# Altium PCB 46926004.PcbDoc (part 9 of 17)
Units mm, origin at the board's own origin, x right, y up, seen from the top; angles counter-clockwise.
Board outline 250 x 200 mm, 6 copper layers (Top Layer, INT1_GND, INT2_SIG, INT3_SIG, INT4_GND, Bottom Layer), stack 1.71 mm thick; 1450 components, 1293 nets, 5656 pads, 2307 vias.
Unrouted connection lines stored in the file: 2.
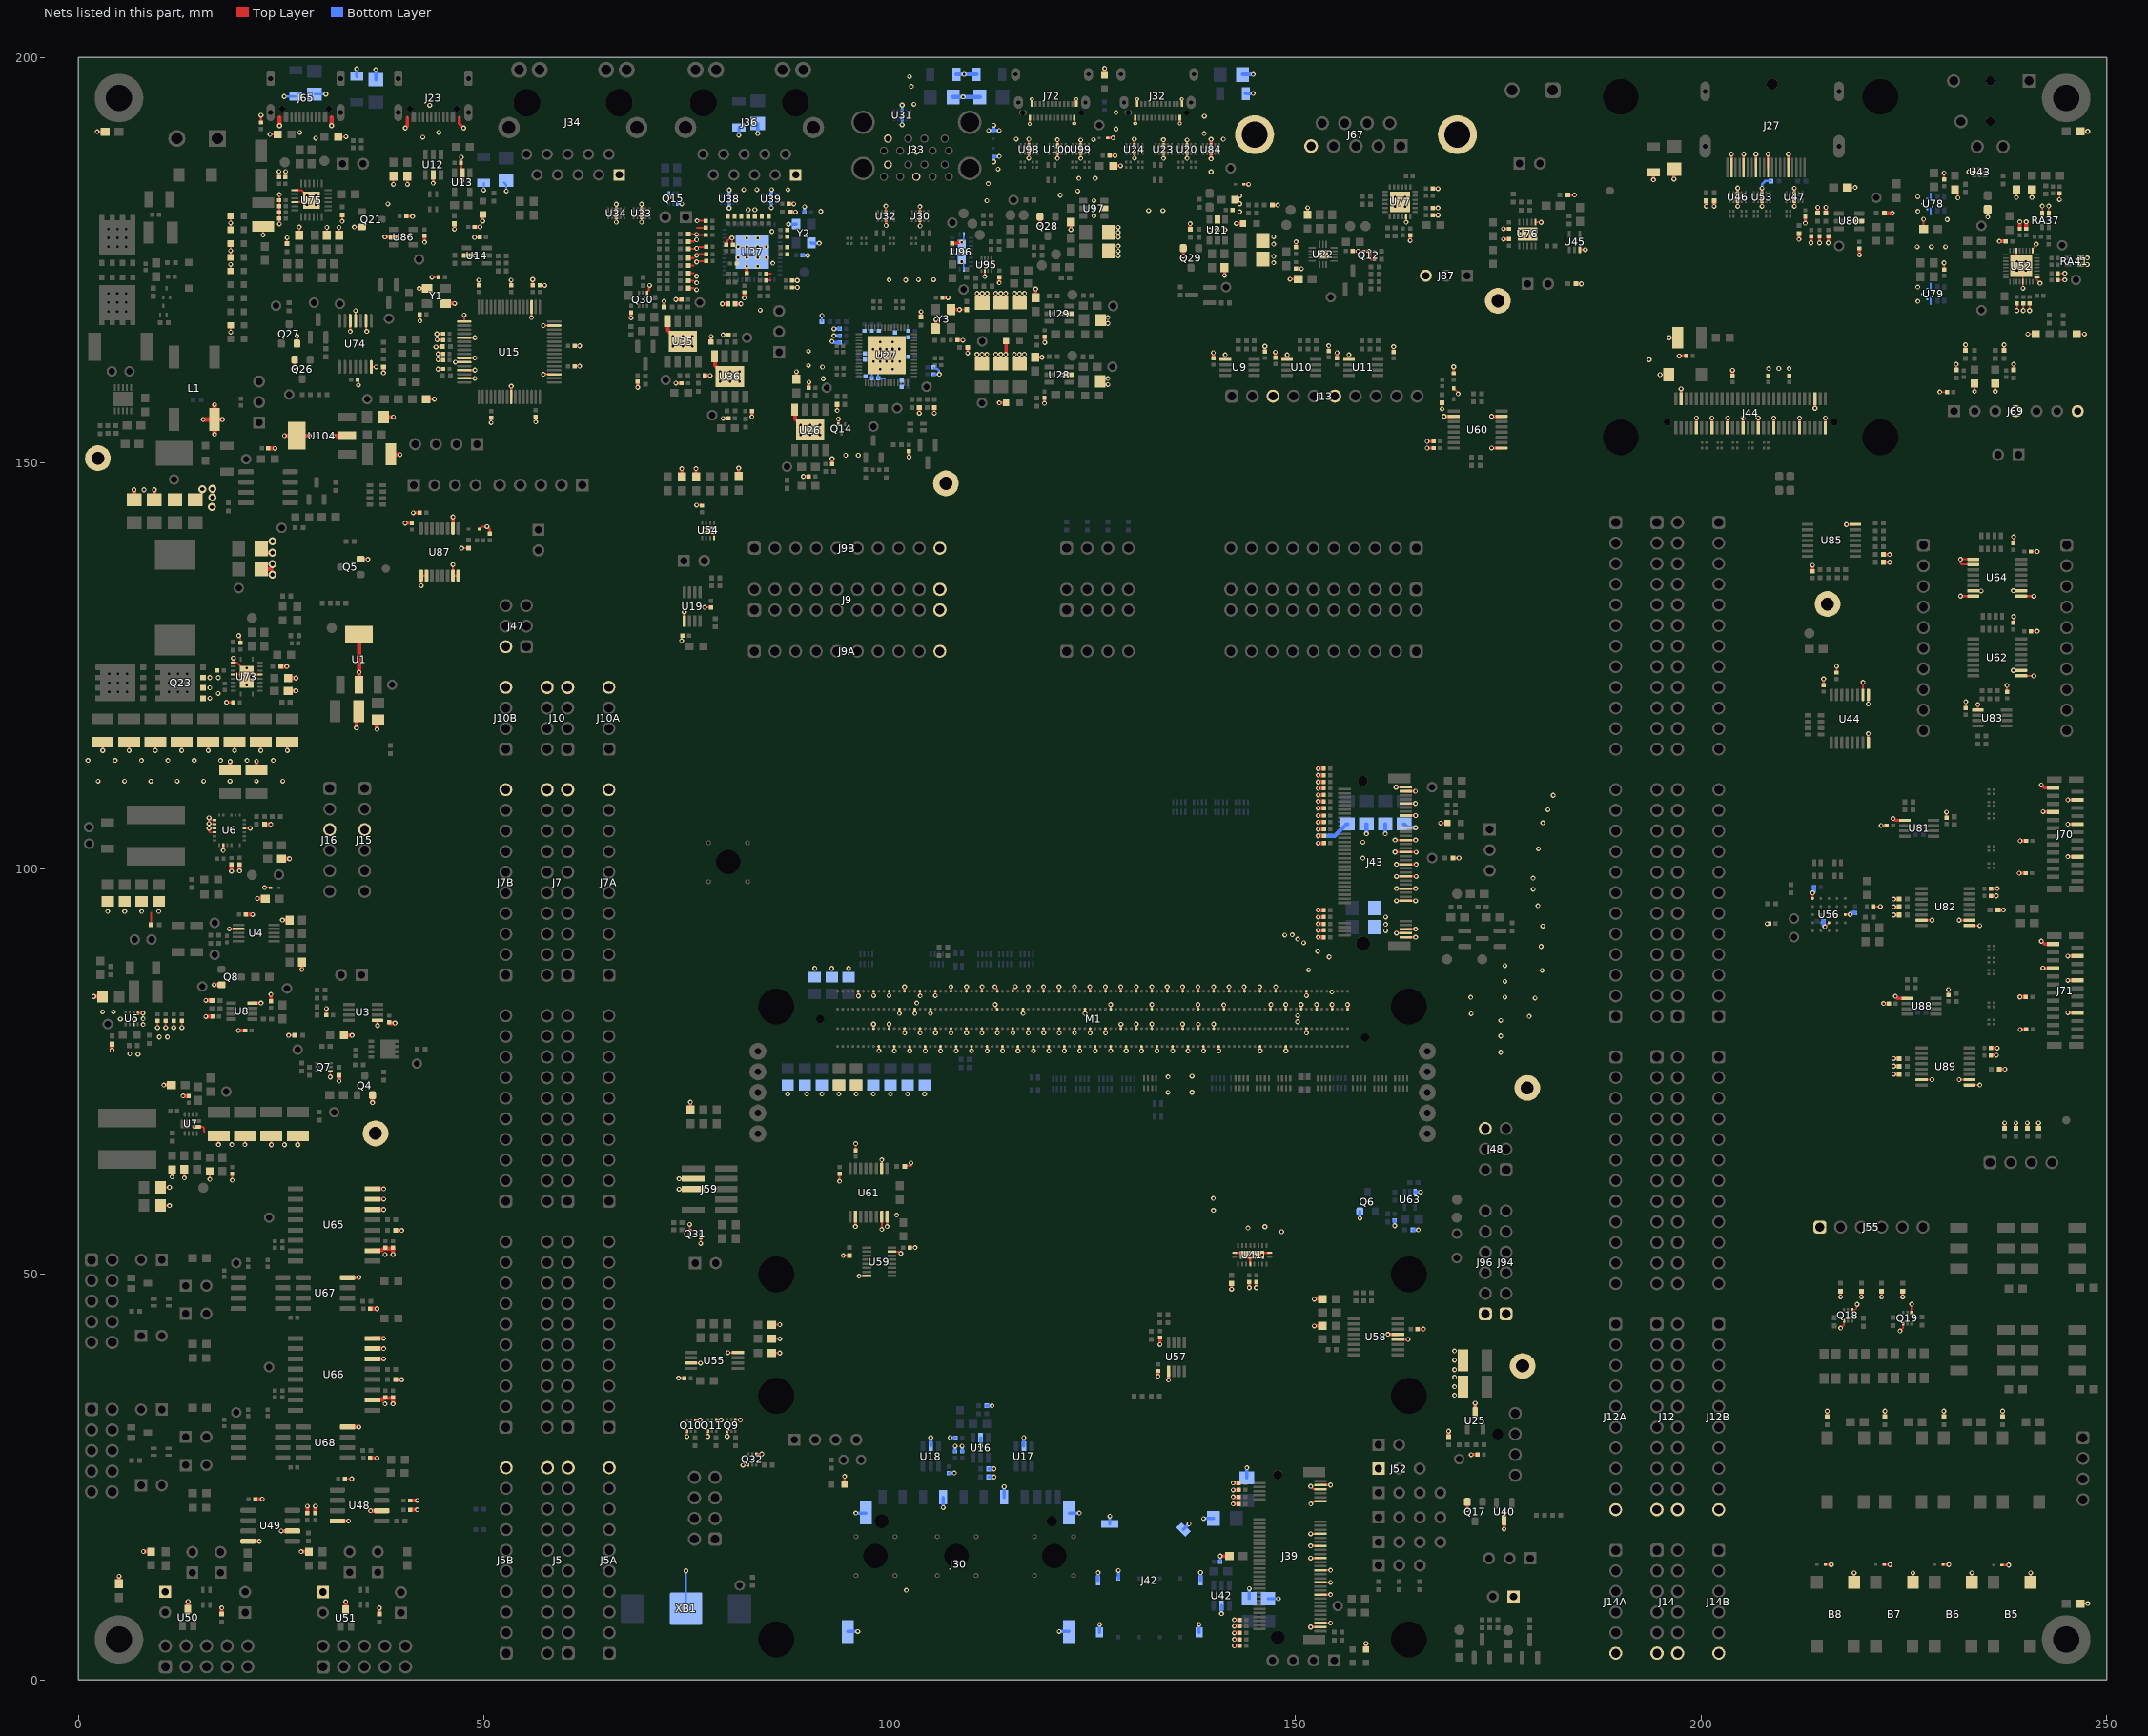
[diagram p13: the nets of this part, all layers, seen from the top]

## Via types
v1: diameter 0.6, hole 0.3, Top Layer to Bottom Layer, tented both sides, 2171 vias
v2: diameter 0.6, hole 0.3, Top Layer to Bottom Layer, 48 vias
v3: diameter 1, hole 0.5, Top Layer to Bottom Layer, tented both sides, 37 vias
v4: diameter 0.5, hole 0.2, Top Layer to Bottom Layer, tented both sides, 34 vias
v5: diameter 0.6, hole 0.3, Top Layer to Bottom Layer, tented bottom, 17 vias

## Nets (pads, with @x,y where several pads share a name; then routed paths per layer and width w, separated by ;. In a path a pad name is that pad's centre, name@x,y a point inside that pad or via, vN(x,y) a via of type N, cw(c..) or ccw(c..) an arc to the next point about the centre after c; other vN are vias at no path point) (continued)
GND: B5.1 B6.1 B7.1 B8.1 C1.1 C4.1 C8.1 C9.1 C12.1 C13.1 C14.1 C15.1 C17.1 C18.1 C19.1 C20.1 C21.1 C22.1 C23.1 C24.1 C25.1 C26.1 C27.1 C28.1 C30.1 C31.1 C32.1 C33.1 C35.1 C36.1 C37.2 C39.2 C40.1 C41.2 C42.1 C43.1 C44.1 C45.1 C46.1 C47.1 C48.1 C49.1 C50.2 C51.1 C52.1 C53.1 C54.1 C55.1 C56.1 C57.1 C58.1 C59.1 C60.1 C61.1 C62.1 C63.1 C64.1 C65.1 C66.1 C67.1 C68.1 C69.1 C70.1 C71.1 C72.2 C73.2 C74.1 C75.1 C76.1 C77.2 C78.1 C79.1 C80.1 C81.2 C82.1 C83.1 C84.1 C85.1 C86.1 C87.1 C88.1 C89.1 C90.1 C91.1 C92.1 C93.1 C94.1 C95.1 C96.1 C97.1 C99.2 C100.1 C101.1 C102.1 C103.1 C104.1 C105.1 C106.1 C107.1 C108.1 C109.1 C110.1 C111.1 C112.1 C113.1 C114.1 C115.1 C116.1 C118.1 C119.1 C121.2 C122.1 C123.1 C124.2 C125.2 C126.2 C127.2 C128.2 C130.2 C139.1 C140.1 C141.1 C142.1 C143.1 C144.1 C145.1 C146.1 C148.1 C149.1 C150.1 C151.1 C152.1 C153.1 C154.1 C155.2 C156.1 C157.1 C158.1 C159.2 C160.1 C161.1 C162.2 C163.1 C164.1 C165.1 C166.1 C167.1 C168.1 C169.1 C170.2 C171.2 C172.2 C173.2 C174.2 C175.2 C176.2 C177.2 C178.2 C179.2 C180.1 C181.1 C182.1 C183.1 C184.1 C185.1 C186.1 C187.1 C189.1 C190.1 C191.1 C192.1 C193.1 C194.1 C195.1 C196.2 C197.2 C198.1 C199.1 C200.1 C201.1 C202.1 C203.1 C204.1 C205.1 C206.1 C207.1 C208.1 C209.1 C210.1 C211.1 C212.1 C213.1 C214.1 C215.2 C216.2 C217.1 C218.1 C219.1 C220.1 C221.1 C222.1 C226.1 C227.1 C228.1 C229.1 C230.1 C231.1 C232.1 C233.1 C234.1 C235.1 C236.1 C237.1 C238.1 C239.1 C240.1 C241.1 C242.1 C243.1 C244.1 C245.1 C246.1 C247.1 C248.1 C249.1 C250.1 C251.1 C252.1 C265.1 C266.1 C267.2 C269.2 C270.2 C271.1 C272.1 C273.1 C274.1 C275.1 C278.1 C280.1 C281.1 C282.1 C283.1 C284.1 C285.1 C286.2 C287.1 C288.1 C289.1 C290.2 C291.2 C292.1 C293.1 C294.1 C295.1 C296.1 C297.1 C298.1 C301.1 C302.1 C304.2 C306.2 C308.2 C309.2 C310.2 C311.1 C312.1 C313.1 C314.1 C315.1 C316.1 C317.1 C318.1 C319.1 C320.1 C321.1 C322.1 C323.1 C324.1 C325.1 C327.2 C328.1 C329.1 C330.1 C331.1 C332.1 C336.1 C338.1 C339.1 C340.1 C341.1 C342.1 C343.1 C344.1 C345.1 C346.1 C347.1 C348.1 C349.1 C350.1 C351.1 C352.1 C353.1 C354.1 C355.1 C358.1 C359.1 C360.1 C361.1 C362.1 C363.1 C364.1 C365.1 C366.1 C367.1 C368.1 C369.1 C370.1 C371.1 C372.1 C373.1 C374.1 C375.1 C376.1 C377.1 C378.1 C379.1 C380.1 C381.1 C382.1 C383.1 C384.1 C385.1 C386.1 C387.1 C388.1 C389.1 C390.1 C392.1 C394.1 D4.2 D5.2 D7.2 D8.1 D9.2 D10.2 D11.2 D13.2 D14.2 D15.1 D18.2 D20.2 D21.2 D25.2 D29.2 D31.1 D33.2 D35.2 D36.1 D37.1 D38.1 D43.2 D45.2 D48.2 D49.2 D50.1 J5.19 J5.20 J5A.10 J5B.10 J7.19 J7.20 J7A.10 J7B.10 J9.19 J9.20 J9A.10 J9B.10 J10.7 J10.8 J10A.4 J10B.4 J12.19 J12.20 J12A.10 J12B.10 J13.3 J13.6 J14.11 J14.12 J14A.6 J14B.6 J15.3 J16.3 J23.A1/B12 J23.B1/A12 J27.2 J27.5 J27.8 J27.11 J27.16 J30.3 J30.6 J30.12 J32.A1 J32.A12 J32.B1 J32.B12 J33.L4 J33.L7 J33.U4 J33.U7 J34.1 J36.1 J39.3 J39.5 J39.11 J39.27 J39.33 J39.39 J39.45 J39.51 J39.57 J39.71 J39.73 J42.9 J42.C5 J43.1 J43.3 J43.9 J43.15 J43.21 J43.27 J43.33 J43.39 J43.45 J43.51 J43.57 J43.71 J43.73 J43.75 J44.3 J44.10 J44.16 J44.22 J44.28 J44.34 J44.40 J44.50 J44.55 J44.60 J47.2 J48.6 J52.1 J55.1 J59.3 J59.5 J65.A1/B12 J65.B1/A12 J67.5 J67.10 J67.11 J69.4 J69.7 J70.1 J70.4 J70.7 J70.10 J70.18 J71.1 J71.4 J71.7 J71.10 J71.18 J72.A1 J72.A12 J72.B1 J72.B12 J76.1 J79.1 J81.1 J87.3 J94.1 J96.1 JP2.1 L1.4 M1.A04 M1.A09 M1.A15 M1.A18 M1.A21 M1.A24 M1.A27 M1.A30 M1.A33 M1.A36 M1.A39 M1.A42 M1.A45 M1.A48 M1.A51 M1.A54 M1.A57 M1.A60 M1.A63 M1.A66 M1.A69 M1.A72 M1.A75 M1.A78 M1.A81 M1.A84 M1.A87 M1.A90 M1.A93 M1.A96 M1.B01 M1.B04 M1.B07 M1.B10 M1.B13 M1.B16 M1.B25 M1.B30 M1.B39 M1.B47 M1.B52 M1.B64 M1.B69 M1.B82 M1.B85 M1.B88 M1.C09 M1.C27 M1.C30 M1.C33 M1.C39 M1.C42 M1.C45 M1.C48 M1.C51 M1.C54 M1.C57 M1.C60 M1.C63 M1.C66 M1.C69 M1.C72 M1.C75 M1.C78 M1.C81 M1.C84 M1.C87 M1.C90 M1.C93 M1.D13 M1.D18 M1.D26 M1.D29 M1.D32 M1.D35 M1.D38 M1.D41 M1.D44 M1.D47 M1.D50 M1.D53 M1.D56 M1.D59 M1.D62 M1.D65 M1.D68 M1.D71 M1.D74 M1.D77 M1.D80 M1.D83 M1.D86 M1.D89 M1.D92 Q4.2 Q5.2 Q6.2 Q7.1 Q8.2 Q9.1 Q9.4 Q10.1 Q10.4 Q11.1 Q11.4 Q12.1 Q12.4 Q14.2 Q15.1 Q15.4 Q17.2 Q18.1 Q18.4 Q19.1 Q19.4 Q21.2 Q23.1 Q23.2 Q23.3 Q26.2 Q27.2 Q28.2 Q29.2 Q30.1 Q31.1 Q31.4 Q32.1 Q32.4 R11.2 R15.1 R16.1 R26.1 R31.1 R34.1 R42.2 R47.1 R49.1 R56.2 R59.1 R80.2 R81.2 R82.2 R85.1 R91.1 R95.2 R97.1 R98.1 R101.2 R107.1 R114.1 R115.2 R120.2 R126.1 R127.1 R130.2 R132.1 R133.1 R134.1 R142.1 R143.1 R148.2 R149.1 R151.1 R153.1 R155.1 R157.1 R161.1 R163.1 R167.1 R171.1 R172.1 R176.1 R179.2 R185.2 R189.2 R190.1 R203.2 R215.2 R218.2 R219.1 R224.1 R225.1 R226.1 R235.1 R236.1 R237.1 R241.1 R243.1 R245.1 R247.1 R251.1 R252.1 R256.2 R257.1 R259.1 R261.1 R263.1 R267.2 R270.2 R272.2 R275.1 R276.1 R277.1 R278.1 R283.1 R285.1 R288.2 R291.1 R292.1 R299.1 R303.1 R304.1 R312.2 R317.1 R319.2 R323.2 R327.2 R330.1 R331.2 R334.1 R338.1 R344.1 R345.1 R352.2 R356.2 R357.2 R360.1 R361.1 R362.1 R366.1 R368.1 R369.1 R370.1 R374.1 R378.1 R379.1 R397.2 R398.2 R399.1 R404.1 R405.2 R419.2 R420.1 R421.1 R438.1 R440.1 R441.1 R447.2 R448.2 R449.2 R451.1 R460.2 R465.2 R473.2 R474.2 RA37.1 RA37.2 RA41.1 RA41.2 U1.2 U1.4 U3.1 U4.7 U5.3 U5.5 U6.4 U6.12 U6.13 U6.14 U6.15 U6.19 U7.5 U8.4 U9.1 U10.1 U11.1 U12.2 U13.2 U14.2 U15.1 U15.5 U15.10 U15.11 U15.13 U15.15 U15.25 U15.35 U15.47 U15.51 U16.2 U17.2 U18.2 U19.1 U20.3 U20.8 U21.2 U22.17 U23.3 U23.8 U24.3 U24.8 U25.3 U26.8 U26.9 U27.57 U28.2 U29.2 U30.3 U30.8 U31.3 U31.8 U32.3 U32.8 U33.3 U33.8 U34.3 U34.8 U35.8 U35.9 U36.8 U36.9 U37.49 U38.3 U38.8 U39.3 U39.8 U40.3 U41.5 U41.11 U41.20 U41.21 U42.2 U43.2 U44.8 U44.9 U44.10 U45.3 U46.3 U46.8 U47.3 U47.8 U48.2 U48.8 U49.2 U49.8 U50.3 U51.3 U52.5 U52.9 U52.17 U52.22 U52.33 U53.3 U53.8 U54.4 U54.9 U55.4 U55.7 U56.B3 U56.C1 U56.E5 U57.1 U58.4 U58.5 U59.8 U59.15 U60.1 U60.7 U60.10 U61.2 U61.7 U61.8 U61.10 U62.9 U62.10 U63.3 U64.1 U64.2 U64.7 U64.8 U64.9 U64.10 U65.2 U65.6 U65.7 U65.8 U66.2 U66.6 U66.7 U66.8 U67.4 U68.4 U73.6 U73.12 U73.15 U73.21 U74.7 U74.9 U74.11 U74.12 U75.19 U75.22 U75.25 U76.6 U76.11 U77.17 U77.25 U78.3 U79.3 U80.2 U81.1 U82.7 U82.9 U82.10 U83.1 U84.3 U84.8 U85.7 U86.2 U87.1 U87.2 U87.7 U87.8 U87.10 U88.1 U89.7 U89.9 U89.10 U95.10 U96.5 U96.11 U96.20 U96.21 U97.2 U98.3 U98.8 U99.3 U99.8 U100.3 U100.8 U104.2 U104.4 X2.1 X4.1 X5.1 X6.1 X7.1 X8.1 X9.1 XB1.1 Y1.2 Y1.4 Y2.2 Y2.4 Y3.2 Y3.4 | length 747.2
  Top Layer w0.15: C14.1@2.972,84.253 C14.1@2.975,84.25 ; U5.3@6.825,80.847 v1(6.825,81.472) ; C215.2@8.957,15.838 C215.2@8.961,15.834 ; v1(9.755,80.414) C26.1@9.755,81.153 ; v1(10.755,80.414) C25.1@10.755,81.153 ; v1(11.755,80.414) C24.1@11.755,81.153 ; v1(12.755,80.414) C21.1@12.755,81.153 ; Q23.1@15.365,121.015 Q23.1@15.37,121.02 ; v1(16.1,106.275) v1@16.167,106.208 ; v1@16.187,121.02 v1(16.192,121.025) ; U6.15@16.795,104.488 16.192,104.488 16.104,104.576 16.104,104.971 v1(16.1,104.975) 16.107,104.982 16.788,104.982 U6.14@16.795,104.989 ; U6.13@16.795,105.489 16.752,105.532 16.143,105.532 v1(16.1,105.575) 16.1,106.141 v1@16.167,106.208 ; U6.12@16.795,105.989 16.396,105.989 16.177,106.208 v1@16.167,106.208 ; U73.12@19.092,125.425 19.095,125.422 19.495,125.422 20.867,124.05 U73.21@20.867,123.8 ; v1(19.76,128.73) 19.76,128.654 19.98,128.434 19.98,127.937 C267.2@19.992,127.925 ; v1@21.159,104.982 v1(21.166,104.975) ; C47.1@23.717,83.783 C47.1@23.725,83.775 ; v1(25.915,79.46) 26.635,79.46 R465.2@26.645,79.45 ; C216.2@28.396,15.825 C216.2@28.4,15.821 ; v1(31.04,74.325) Q7.1@31.04,75.05 ; C209.1@32.925,24.8 v1(33.675,24.8) ; U66.2@36.248,34.5 U66.2@36.263,34.485 ; U54.9@78.17,141.713 78.17,141.619 78.37,141.419 U54.4@78.37,140.763 ; R247.1@215.537,32.464 v1(215.537,33.139) ; v1(217.202,43.37) 217.6,43.768 217.6,44.265 Q18.4@217.61,44.275 ; R438.1@218.025,183.967 v1(219,183.967) ; Q18.1@218.61,45.625 218.985,45.625 219.139,45.779 219.139,46.214 v1(219.225,46.3) ; R245.1@222.662,32.464 v1(222.662,33.139) ; v1(224.517,43.02) 224.915,43.418 224.915,43.915 Q19.4@224.925,43.925 ; Q19.1@225.925,45.275 225.937,45.288 225.937,46.312 v1(225.95,46.325) ; v1(229.421,158.775) C342.1@230.2,158.775 ; R243.1@229.912,32.464 v1(229.912,33.139) ; C182.1@229.95,173.975 v1(229.95,174.675) ; v1(235.325,180.325) JP2.1@235.325,181.275 ; R241.1@237.162,32.464 v1(237.162,33.139) ; v1(238.875,182.75) C184.1@238.875,183.7 ; v1(238.925,168.796) C218.1@238.925,169.575 ; v1(239.7,168.796) C219.1@239.7,169.575 ; v1(240.275,165.9) C341.1@241.225,165.9 ; v1(240.475,168.796) C221.1@240.475,169.575 ; v1(240.775,182.75) C336.1@240.775,183.7 ; RA37.2@242.05,180.728 v1(242.05,181.678) ; RA37.1@242.85,180.728 v1(242.85,181.678) ; C227.1@244.075,172.575 v1(244.825,172.575) ; C226.1@244.075,173.4 v1(244.825,173.4) ; v1(244.175,182.475) C327.2@244.175,183.175 ; C338.1@246.3,165.9 v1(247.25,165.9) ; R11.2@246.704,9.421 v1(247.65,9.421) ; R449.2@246.704,190.896 v1(247.65,190.896) ; RA41.1@246.81,174.475 v1(247.589,174.475) ; RA41.2@246.81,175.275 v1(247.589,175.275)
  Top Layer w0.2: C9.1@30.577,81.975 v1@30.577,82.76 ; v1(108.587,168.918) 109.495,168.918 R379.1@109.499,168.914 ; v1(111.716,172.988) U95.10@111.716,173.711 ; C314.1@230.233,106.303 v1@230.233,106.968 ; C320.1@230.47,84.45 v1@230.47,85.115 ; U52.22@238.871,176.2 238.871,174.875 v2(238.921,174.825) U52.33@239.471,174.275 239.671,174.075 U52.5@239.671,172.35 239.671,171.564 v1(239.68,171.555) ; U52.17@240.871,176.2 240.871,176.469 241.3,176.898 v1(241.3,176.976) ; U52.9@241.396,172.875 241.396,172.554 v1(241.775,172.175)
  Top Layer w0.25: v1(2.3,190.85) R448.2@3.275,190.85 ; v1(2.992,114.575) C278.1@2.992,115.575 ; v1(6.242,114.575) C281.1@6.242,115.575 ; U5.5@7.325,82.197 v1(7.95,82.197) ; R26.1@8.965,93.075 8.965,94.575 ; v1(9.492,114.575) C275.1@9.492,115.575 ; C15.1@10.152,58.475 v1(11.228,58.475) ; C13.1@10.152,60.725 v1(11.228,60.725) ; v1(11.525,62) C30.1@11.525,62.95 ; v1(12.742,114.575) C274.1@12.742,115.575 ; v1(13.052,61.875) R49.1@13.052,62.95 ; U7.5@14.559,68.192 15.338,68.192 15.484,68.046 15.484,67.642 15.509,67.617 ; v1(15.992,114.575) C273.1@15.992,115.575 ; v1(16.2,61.7) C37.2@16.2,62.775 ; v1(17.28,66) C331.1@17.28,67.075 ; v1(17.845,102.25) 17.869,102.275 U6.19@17.869,102.913 ; v1(18.253,120.5) C270.2@18.992,120.5 ; v1(18.6,92.575) U4.7@19.725,92.575 ; D7.2@18.75,173.675 18.77,173.695 v1(18.77,174.474) ; D5.2@18.75,175.35 18.77,175.37 v1(18.77,176.181) 18.77,177.03 D49.2@18.75,177.05 ; D48.2@18.75,178.75 18.77,178.77 v1(18.77,179.6) 18.77,180.43 D4.2@18.75,180.45 ; v1(18.775,166.15) D9.2@18.775,166.975 ; v1(18.954,61.592) C36.1@18.954,62.317 ; U73.15@19.092,123.925 20.492,123.925 U73.21@20.742,123.675 20.867,123.8 20.992,123.925 U73.6@22.392,123.925 ; U73.12@19.092,125.425 v1(19.092,125.95) ; v1(19.242,114.575) C272.1@19.242,115.575 ; U6.4@20.445,104.989 v1@21.152,104.989 ; v1(20.53,66) C332.1@20.53,67.075 ; v1(22.492,114.575) C266.1@22.492,115.575 ; C289.1@22.5,192.075 v1(22.5,192.875) ; v1(22.76,178.115) C293.1@22.76,179.19 ; v1(22.943,97.675) D43.2@23.693,97.675 ; v1(23.6,190.5) C291.2@24.55,190.5 ; v1(23.78,65.983) 23.78,67.075 C43.1@23.786,67.081 ; C292.1@24.65,182.4 24.767,182.517 24.767,183.084 v1(24.784,183.101) ; C297.1@24.725,185.25 v1(24.725,185.944) ; C292.1@24.75,182.4 C294.1@24.75,181.65 C295.1@24.75,180.9 C298.1@24.75,180.15 24.765,180.135 24.765,179.485 v1(24.78,179.47) ; C296.1@25.525,185.25 25.53,185.255 25.53,185.944 v1(25.535,185.949) ; R334.1@25.725,177.053 v1(25.725,177.778) ; v1(25.742,114.575) C265.1@25.742,115.575 ; Q26.2@26.65,162.756 26.658,162.749 26.658,161.794 v1(26.665,161.786) ; U75.22@26.675,182.15 27.875,182.15 v2(28.175,181.85) ; U75.19@26.675,183.65 27.475,183.65 v2(28.175,182.95) ; Q27.2@26.925,164.725 v1(26.925,165.65) ; v1(27.026,65.983) 27.026,67.075 C40.1@27.032,67.081 ; R338.1@27.225,178.103 v1(27.225,179.103) ; R330.1@30.625,178.085 v1(30.625,179.051) ; C290.2@32.025,190.225 v1(32.975,190.225) ; R331.2@32.125,178.084 v1(32.125,179.05) ; v1(32.5,179.8) R317.1@32.5,180.6 ; v1(33.5,166.235) U74.12@33.5,167.55 ; v1(34,179.1) Q21.2@34.94,179.1 ; U74.11@34.15,167.55 v1(34.15,168.79) ; v1(34.5,159.625) C287.1@34.5,160.3 ; Q5.2@34.764,138.15 v1(35.689,138.15) ; U74.9@35.45,167.55 35.469,167.531 35.469,166.414 35.553,166.33 v1(35.553,166.235) ; U74.7@36.1,161.85 v1(36.695,161.85) ; v1(37.6,161.125) R327.2@37.6,161.85 ; C284.1@38.525,151.075 C284.1@38.55,151.05 ; v1(38.813,184.345) R80.2@38.813,185.37 ; v1(40.55,184.35) R81.2@40.55,185.375 ; v1(42.09,167.525) C77.2@42.09,168.325 ; v1(42.265,134.876) U87.1@42.265,136.136 U87.2@42.915,136.136 ; R323.2@42.865,157.868 v1(43.865,157.868) ; Y1.4@42.99,171.525 Y1.4@43.09,171.525 ; v1(43.59,172.9) C81.2@44.39,172.9 ; v1(43.725,184.5) U12.2@43.725,185.525 ; v1(44.065,164.325) 44.077,164.337 44.828,164.337 R91.1@44.84,164.35 ; v1(44.188,165.925) 44.2,165.937 44.828,165.937 C80.1@44.84,165.95 ; v1(44.205,165.2) 44.217,165.188 44.828,165.188 C76.1@44.84,165.175 ; v1(44.312,161.575) 44.324,161.587 44.805,161.587 44.84,161.622 C83.1@44.84,161.65 ; v1(44.312,162.725) 44.324,162.712 44.827,162.712 C75.1@44.84,162.7 ; v1(44.312,163.45) 44.324,163.462 44.828,163.462 C79.1@44.84,163.475 ; R91.1@44.815,164.175 R91.1@44.84,164.2 ; v1(46.175,137.486) 46.165,137.475 U87.7@46.165,136.136 U87.8@46.815,136.136 ; v1(46.45,162.437) 46.456,162.444 47.544,162.444 U15.11@47.55,162.45 ; v1(47.197,187.692) 47.175,187.67 47.175,187.052 C72.2@47.153,187.03 47.222,186.961 47.222,185.857 U13.2@47.291,185.788 ; v1(47.24,139.5) R95.2@48.1,139.5 ; U15.15@47.55,160.45 v1(48.865,160.45) ; U15.13@47.55,161.45 v1(48.865,161.45) ; U15.10@47.55,162.95 v1(48.865,162.95) ; U15.5@47.55,165.45 v1(48.865,165.45) ; U15.1@47.55,167.45 v1(47.55,168.25) ; U14.2@47.845,175.566 47.849,175.571 48.886,175.571 v1(48.89,175.575) ; v1(48.825,177.816) C74.1@49.45,177.816 ; C86.1@49.34,171.9 v1(49.34,172.534) ; D10.2@49.44,141.865 49.751,142.176 v1(50.35,142.176) 50.7,141.826 C392.1@50.7,141.3 ; v1(50.865,154.975) C85.1@50.865,155.6 ; v1(53.325,172.534) 53.333,172.527 53.333,171.907 C89.1@53.34,171.9 ; U15.25@53.35,158.15 v1(53.35,159.465) ; v1(55.85,167.935) U15.51@55.85,169.25 ; v1(55.99,172.619) 55.995,172.614 C78.1@55.995,172.005 ; v1(56.365,155.075) C87.1@56.365,155.7 ; C82.1@56.85,171.9 v1(57.475,171.9) ; v1(57.335,160.95) U15.35@58.65,160.95 ; v1(57.335,166.95) U15.47@58.65,166.95 ; C84.1@61.15,161.95 v1(61.775,161.95) ; C88.1@61.15,164.45 v1(61.775,164.45) ; v1(66.3,179.7) U34.8@66.3,180.353 ; U34.3@66.3,181.195 v1(66.3,181.9) ; v1(69.4,179.7) U33.8@69.4,180.35 ; U33.3@69.4,181.167 v1(69.4,181.9) ; Q30.1@70.076,170.969 70.076,171.104 70.334,171.362 70.334,171.823 v1(70.401,171.89) ; v1(73.978,37.215) C233.1@74.675,37.215 ; v1(74.025,60.5) J59.5@75.19,60.5 ; v1(74.025,61.775) 74.025,61.773 75.262,61.773 J59.3@75.265,61.77 ; v1(74.35,128.1) C92.1@74.35,128.755 ; U19.1@74.675,130.535 v1(74.675,131.65) ; Q10.1@75.003,30.676 75.013,30.666 75.013,30.004 v1(75.017,30) ; R151.1@75.17,171.562 75.836,171.562 ; R149.1@75.17,172.487 75.836,172.487 ; R157.1@75.17,173.412 75.836,173.412 ; R451.1@75.17,174.337 75.836,174.337 ; R219.1@75.17,175.262 75.836,175.262 ; R161.1@75.17,176.387 75.836,176.387 ; R167.1@75.17,177.312 75.836,177.312 ; R163.1@75.17,178.237 75.836,178.237 ; Q31.4@75.35,55.475 v1(75.35,56.15) ; U55.7@75.475,39.05 v1(76.675,39.05) ; Q10.4@76.009,32.031 76.015,32.026 76.61,32.026 v1(76.616,32.02) ; v1(76.195,144.813) 76.207,144.826 76.857,144.826 C228.1@76.875,144.843 ; v1@76.195,174.9 C156.1@77.375,174.9 ; v1@76.195,175.75 C179.2@77.375,175.75 ; v1@76.195,176.65 C167.1@77.375,176.65 ; v1@76.245,178.11 C130.2@77.325,178.11 ; 76.245,179.01 C142.1@77.325,179.01 ; v1(76.245,179.86) C143.1@77.325,179.86 ; v1(76.7,53.8) Q31.1@76.7,54.475 ; v1(77.175,132.213) C93.1@77.96,132.213 ; v1(77.57,30.025) 77.582,30.038 77.582,30.68 Q11.1@77.599,30.696 ; Q11.4@78.601,32.044 v1@79.196,32.044 ; C157.1@79.85,177.025 79.975,177.15 79.975,177.416 80.242,177.683 80.483,177.683 v1(80.55,177.75) 80.6,177.7 80.6,177.075 C161.1@80.65,177.025 ; v1(79.97,30.029) 79.972,30.031 Q9.1@79.972,30.703 ; v1(80.075,40.35) U55.4@81.275,40.35 ; Q9.4@80.981,32.044 v1@81.576,32.044 ; v1(81.9,26.475) 82.55,26.475 Q32.1@82.575,26.5 ; Q32.4@83.575,27.85 v1(84.225,27.85) ; C174.2@84.788,172.525 85.338,172.525 ; C165.1@84.788,173.35 85.338,173.35 ; R237.1@85.45,43.8 v1(86.45,43.8) ; v1(93.52,156.481) R134.1@93.52,157.23 ; Q14.2@93.67,154.781 v1(93.67,155.431) ; v1(93.814,61.475) C239.1@93.814,62.314 ; v1(94.266,52.3) R283.1@95.015,52.3 ; D14.2@94.425,24.1 v1(94.425,25.1) ; v1(95.764,55.901) U61.2@95.764,57.114 ; C240.1@95.8,65.3 v1(95.8,66.125) ; M1.A96@96.108,84.9 96.12,84.888 96.12,84.33 v1(96.132,84.318) ; v1(96.225,49.775) 96.237,49.788 97.174,49.788 U59.8@97.187,49.8 ; v1(98,80.85) 98.006,80.844 M1.C93@98.006,80.306 ; M1.A93@98.013,84.9 98.019,84.894 98.019,84.356 v1(98.025,84.35) ; M1.D92@98.653,78.094 98.661,78.086 98.661,77.589 v1(98.675,77.575) ; v1(99.014,55.539) U61.7@99.014,56.814 ; U61.10@99.014,63.314 99.014,64.1 v1(99.014,64.125) ; U32.3@99.517,180.855 v1(99.517,181.688) ; v1@99.53,179.3 U32.8@99.53,180.025 ; v1(99.664,55.901) U61.8@99.664,57.114 ; v1(99.905,80.85) 99.911,80.844 M1.C90@99.911,80.306 ; v1(99.912,84.361) 99.918,84.367 M1.A90@99.918,84.9 ; U59.15@100.263,52.8 101.057,52.8 101.266,52.591 v1(101.361,52.591) ; M1.D89@100.558,78.094 100.558,77.556 v1(100.565,77.55) ; M1.B88@101.193,82.694 101.193,82.156 v1(101.2,82.15) ; v1(101.817,85.439) 101.82,85.436 101.82,84.903 M1.A87@101.823,84.9 ; M1.C87@101.828,80.294 101.828,79.756 v1(101.835,79.75) ; R285.1@101.864,63.314 101.92,63.369 102.57,63.369 102.625,63.425 v1(102.625,63.725) ; C238.1@102.45,53.3 v1(103.125,53.3) ; M1.D86@102.463,78.094 102.463,77.556 v1(102.47,77.55) ; M1.B85@103.098,82.694 103.098,82.156 v1(103.105,82.15) ; U30.8@103.725,180.892 v1@103.725,181.617 ; M1.A84@103.728,84.9 103.734,84.894 103.734,84.331 v1(103.74,84.325) ; M1.C84@103.733,80.294 103.733,79.756 v1(103.74,79.75) ; v1(103.737,179.229) U30.3@103.737,180.062 ; M1.D83@104.368,78.094 104.368,77.556 v1(104.375,77.55) ; M1.B82@105.003,82.694 105.003,82.156 v1(105.01,82.15) ; v1(105.626,84.363) 105.633,84.37 M1.A81@105.633,84.9 ; M1.C81@105.638,80.294 105.638,79.756 v1(105.645,79.75) ; M1.D80@106.273,78.094 106.273,77.556 v1(106.28,77.55) ; M1.A78@107.538,84.9 v1@107.537,85.443 ; M1.C78@107.543,80.294 107.543,79.756 v1(107.55,79.75) ; M1.D77@108.178,78.094 108.178,77.556 v1(108.185,77.55) ; M1.A75@109.443,84.9 109.449,84.906 109.449,85.438 v1(109.455,85.444) ; M1.C75@109.448,80.294 109.448,79.756 v1(109.455,79.75) ; M1.D74@110.083,78.094 110.083,77.556 v1(110.09,77.55) ; M1.A72@111.348,84.9 111.361,84.913 111.361,85.424 v1(111.375,85.438) ; M1.C72@111.353,80.294 111.353,79.756 v1(111.36,79.75) ; M1.D71@111.988,78.094 111.988,77.556 v1(111.995,77.55) ; v1(112.975,85.45) 113.253,85.172 M1.A69@113.253,84.9 ; v1(113,83.25) 113.067,83.183 113.067,82.914 113.246,82.735 M1.B69@113.246,82.706 ; M1.C69@113.258,80.294 113.258,79.756 v1(113.265,79.75) ; M1.D68@113.893,78.094 113.893,77.556 v1(113.9,77.55) ; M1.A66@115.158,84.9 115.158,85.158 v1(115.475,85.475) ; M1.C66@115.163,80.294 115.163,79.756 v1(115.17,79.75) ; M1.D65@115.798,78.094 115.798,77.556 v1(115.805,77.55) ; M1.B64@116.433,82.694 116.433,82.156 v1(116.44,82.15) ; v1(117.05,85.45) 117.056,85.444 M1.A63@117.056,84.906 ; M1.C63@117.068,80.294 117.07,80.292 117.07,79.758 v1(117.078,79.75) ; U98.3@117.137,189.088 v1(117.137,189.921) ; v1(117.15,187.583) U98.8@117.15,188.258 ; v4(117.239,191.805) J72.A12@117.239,192.505 ; M1.D62@117.703,78.094 117.703,77.556 v1(117.71,77.55) ; v1(118.955,85.45) 118.961,85.444 M1.A60@118.961,84.906 ; M1.C60@118.973,80.294 118.973,79.756 v1(118.98,79.75) ; M1.D59@119.608,78.094 119.608,77.556 v1(119.615,77.55) ; v1(120.675,187.557) U100.8@120.675,188.258 ; U100.3@120.675,189.1 v1(120.675,189.85) ; v1(120.86,85.45) 120.866,85.444 M1.A57@120.866,84.906 ; M1.C57@120.878,80.294 120.878,79.756 v1(120.885,79.75) ; M1.D56@121.513,78.094 121.513,77.556 v1(121.52,77.55) ; v4(122.75,191.85) J72.A1@122.75,192.55 ; v1(122.765,85.45) 122.771,85.444 M1.A54@122.771,84.906 ; M1.C54@122.783,80.294 122.783,79.756 v1(122.79,79.75) ; M1.D53@123.418,78.094 123.418,77.556 v1(123.425,77.55) ; U99.3@123.523,189.088 123.543,189.107 123.543,189.818 v1(123.55,189.825) ; U99.8@123.535,188.258 U99.8@123.535,188.258 123.536,187.568 v1(123.537,187.567) ; M1.B52@124.053,82.694 124.053,82.156 v1(124.06,82.15) ; v1(124.67,85.45) 124.676,85.444 M1.A51@124.676,84.906 ; M1.C51@124.688,80.294 124.688,79.756 v1(124.695,79.75) ; M1.D50@125.323,78.094 125.323,77.556 v1(125.33,77.55) ; v1(126.575,85.45) 126.581,85.444 M1.A48@126.581,84.906 ; M1.C48@126.593,80.294 126.593,79.756 v1(126.6,79.75) ; v1(127.21,83.25) 127.216,83.244 M1.B47@127.216,82.706 ; v1(127.223,77.582) M1.D47@127.222,78.1 ; v1(128.48,85.45) 128.486,85.444 M1.A45@128.486,84.906 ; M1.C45@128.486,80.306 128.493,80.313 v1(128.494,80.836) v1(128.494,80.836) ; M1.D44@129.133,78.094 129.133,77.556 v1(129.14,77.55) ; U24.3@130.137,189.088 v1(130.137,189.921) ; v1(130.15,187.583) U24.8@130.15,188.258 ; v4(130.25,191.85) J32.A12@130.25,192.55 ; v1(130.385,80.85) 130.391,80.844 M1.C42@130.391,80.306 ; v1(130.385,85.45) 130.391,85.444 M1.A42@130.391,84.906 ; M1.D41@131.038,78.094 131.038,77.556 v1(131.045,77.55) ; v1(132.29,80.85) 132.296,80.844 M1.C39@132.296,80.306 ; v1(132.29,83.25) 132.296,83.244 M1.B39@132.296,82.706 ; v1(132.29,85.45) 132.296,85.444 M1.A39@132.296,84.906 ; M1.D38@132.943,78.094 132.943,77.556 v1(132.95,77.55) ; v1(133.725,189.85) 133.737,189.837 133.737,189.113 U23.3@133.75,189.1 ; v1(133.75,187.557) U23.8@133.75,188.258 ; v1(134.195,85.45) 134.201,85.444 M1.A36@134.201,84.906 ; M1.D35@134.836,78.106 M1.D35@134.854,78.124 ; M1.D35@134.848,78.094 134.848,77.556 v1(134.855,77.55) ; v4(135.75,191.85) J32.A1@135.75,192.55 ; v1(136.1,80.85) 136.106,80.844 M1.C33@136.106,80.306 ; v1(136.1,85.45) 136.106,85.444 M1.A33@136.106,84.906 ; v1@136.636,187.568 U20.8@136.636,188.257 ; U20.3@136.643,189.107 v1@136.643,189.818 ; M1.D32@136.753,78.094 136.753,77.556 v1(136.76,77.55) ; v1(138.005,83.25) 138.011,83.244 M1.B30@138.011,82.706 ; v1(138.005,85.45) 138.011,85.444 M1.A30@138.011,84.906 ; M1.C30@138.011,80.306 138.037,80.333 138.037,80.812 v1(138.057,80.832) ; M1.D29@138.658,78.094 138.663,78.088 138.663,77.561 v1(138.675,77.55) ; v1(139.908,85.45) 139.915,85.443 139.915,84.907 M1.A27@139.916,84.906 ; v1(139.91,80.85) 139.916,80.844 M1.C27@139.916,80.306 ; M1.D26@140.563,78.094 140.563,77.556 v1(140.57,77.55) ; v1(141.175,83.21) 141.183,83.201 141.183,82.709 M1.B25@141.186,82.706 ; v1(141.35,163.355) 141.35,162.785 U9.1@141.36,162.775 ; v1(141.815,85.45) 141.821,85.444 M1.A24@141.821,84.906 ; U41.20@142.523,52.65 143.298,52.65 143.473,52.475 v1(143.473,52.4) ; v1(143.665,85.45) 143.712,85.402 143.712,84.92 M1.A21@143.733,84.9 ; U41.5@144.423,51.25 144.423,52.15 v1(144.673,52.4) ; v1(145.614,85.45) 145.626,85.438 145.626,84.911 M1.A18@145.631,84.906 ; M1.D18@145.643,78.094 145.643,77.556 v1(145.65,77.55) ; v1(145.873,52.4) 145.873,52.475 146.048,52.65 U41.11@146.823,52.65 ; C67.1@146.234,163.755 146.258,163.779 146.235,163.803 v1(146.235,164.395) ; M1.B16@146.901,82.706 146.927,82.733 146.927,83.202 v1(146.982,83.257) ; M1.A15@147.536,84.906 147.553,84.923 147.553,85.439 v1(147.564,85.45) ; v1(148.8,83.25) 148.806,83.244 M1.B13@148.806,82.706 ; M1.D13@148.818,78.094 148.818,77.556 v1(148.825,77.55) ; v1(150.705,83.25) 150.711,83.244 M1.B10@150.711,82.706 ; M1.C09@151.358,80.294 151.358,79.756 v1(151.365,79.75) ; M1.A09@151.358,84.894 151.358,84.356 v1(151.365,84.35) ; v1(151.875,6.525) J39.73@153.1,6.525 ; v1(151.875,15.025) J39.39@153.1,15.025 ; v1(151.875,16.525) J39.33@153.1,16.525 ; v1(151.875,18.025) J39.27@153.1,18.025 ; v1(151.875,23.875) 152.2,23.55 153.075,23.55 J39.5@153.1,23.525 ; v1(151.9,21.7) 151.921,21.7 152.221,22 153.075,22 J39.11@153.1,22.025 ; v1(152.61,83.25) 152.616,83.244 M1.B07@152.616,82.706 ; J39.71@153.1,7.025 v1(154.325,7.025) ; J39.57@153.1,10.525 v1(154.325,10.525) ; J39.51@153.1,12.025 v1(154.325,12.025) ; J39.45@153.1,13.525 v1(154.325,13.525) ; J39.3@153.1,24.025 v1(154.325,24.025) ; C68.1@154.097,163.82 v1(154.097,164.47) ; v1(154.514,84.808) 154.514,84.899 M1.A04@154.521,84.906 ; v1(154.515,83.25) 154.521,83.244 M1.B04@154.521,82.706 ; v1(156.42,83.25) 156.426,83.244 M1.B01@156.426,82.706 ; v1(156.59,163.355) 156.59,162.785 U11.1@156.6,162.775 ; C70.1@162.1,163.7 v1(162.1,164.35) ; v1@163.65,179.689 U77.17@163.65,180.185 ; U77.17@163.65,180.375 163.656,180.369 U77.17@163.656,180.185 ; v1(168.083,156.68) R189.2@168.083,157.41 ; D13.2@169.5,159.225 170.05,158.675 v1(170.05,158.544) ; C394.1@169.5,161.075 v1(169.5,161.873) ; U76.6@179.6,179.679 v1@180.271,179.679 ; U56.E5@213.75,96.35 v1(213.75,97.025) ; C242.1@215.1,122.725 v1(215.1,123.4) ; v1(215.25,92.85) U56.B3@215.75,93.35 ; C244.1@216.707,124.279 v1(216.707,124.954) ; v1(217.2,47.225) R278.1@217.2,47.9 ; U56.C1@217.755,94.355 v1@218.37,94.355 ; v1(217.904,142.425) U85.7@219.021,142.425 ; v1(219.75,47.225) R277.1@219.75,47.9 ; U44.10@219.95,121.725 v1@219.95,122.978 ; U44.8@220.6,115.525 v1(220.6,116.642) ; v1(220.6,120.3) U44.9@220.6,121.425 ; C230.1@221.415,95.35 v1(222.09,95.35) ; v1(222.25,47.225) R276.1@222.25,47.9 ; v1(224.85,47.225) R275.1@224.85,47.9 ; U89.7@227.179,73.998 v1(228.454,73.998) ; U82.7@227.18,93.65 v1(228.455,93.65) ; R299.1@227.425,178.825 v1(227.425,180.05) ; C144.1@229.95,185.05 v1(229.95,185.75) ; C189.1@231.3,183.7 231.65,183.35 v1(231.65,182.696) ; R215.2@231.45,161.5 v1(231.45,162.175) ; v1@231.816,73.987 U89.10@233.068,73.987 ; v1@231.816,93.639 U82.10@233.068,93.639 ; v1@231.997,133.6 U64.8@233.25,133.6 ; R421.1@232.6,163.9 v1(232.6,164.575) ; C351.1@232.625,119.9 v1(232.625,120.575) ; v1(233,185.9) 233,185.875 U43.2@233.66,185.875 ; U89.9@233.079,73.348 v1(234.354,73.348) ; U82.9@233.08,93 v1(234.355,93) ; U64.7@233.25,134.25 U64.7@233.55,134.25 v1@234.503,134.25 ; U64.2@233.25,137.5 232.121,137.5 231.975,137.646 v1(231.975,138.15) U64.1@233.25,138.15 ; v1(233.7,158.833) C340.1@233.7,159.8 ; U83.1@234.105,119.55 v1(234.105,120.225) ; v1(236.25,158.833) C339.1@236.25,159.8 ; R420.1@237.35,163.9 v1(237.35,164.575) ; R259.1@237.4,68 v1(237.4,68.675) ; C352.1@237.7,121.9 v1(237.7,122.575) ; v1@238.497,124.425 U62.10@239.45,124.425 U62.10@239.75,124.425 ; v1@238.497,134.25 U64.10@239.45,134.25 U64.10@239.75,134.25 ; C243.1@238.5,130.4 v1(238.5,131.075) ; C246.1@238.5,140.225 v1(238.5,140.9) ; R419.2@238.5,161.5 v1(238.5,162.175) ; R263.1@238.8,68 v1(238.8,68.675) ; U62.9@239.75,123.775 v1@241.003,123.775 ; U64.9@239.75,133.6 v1@241.003,133.6 ; R257.1@240.2,68 v1(240.2,68.675) ; C241.1@240.75,129.275 v1(241.425,129.275) ; C245.1@240.75,139.1 v1(241.425,139.1) ; R261.1@241.6,68 v1(241.6,68.675) ; v1(242.125,87.77) v1@242.145,87.75 ; J71.7@243.37,87.75 J71.7@243.398,87.723
  Top Layer w0.3: R235.1@85.45,40.3 v1(86.45,40.3) ; R236.1@85.45,42.05 v1(86.45,42.05) ; J72.B1@117.5,194.25 v4(117.5,194.85) ; J72.B12@123,194.25 v4(123,194.85) ; J32.B1@130.5,194.25 v4(130.5,194.85) ; J32.B12@136,194.25 v4(136,194.85) ; D50.1@143.627,184.355 v1(144.229,184.355) ; v1(149.346,172.665) R107.1@150.346,172.665 ; C355.1@151.496,180.59 151.51,180.604 v1(151.51,181.47) ; Q12.1@158.396,176.115 159.063,176.115 v1(159.067,176.112) 159.221,175.957 159.221,175.215 159.25,175.186 159.321,175.115 Q12.4@159.746,175.115 ; v1(162.275,102.05) J43.33@163.6,102.05 v1(164.875,102.049) v1(164.875,102.049) ; v1(162.275,103.55) J43.27@163.6,103.55 v1(164.8,103.55) ; v1(162.4,110.05) J43.1@163.6,110.05 ; v1(162.45,92.05) J43.73@163.6,92.05 ; v1(162.45,96.056) 162.456,96.05 J43.57@163.6,96.05 v1(164.8,96.05) ; v1(162.45,99.044) 162.456,99.05 J43.45@163.6,99.05 v1(164.875,99.05) ; v1(162.45,100.55) J43.39@163.6,100.55 v1(164.875,100.55) ; v1(162.456,97.55) J43.51@163.6,97.55 v1(164.8,97.55) ; J43.75@163.6,91.55 v1(164.8,91.55) ; J43.71@163.6,92.55 v1(164.8,92.55) ; J43.21@163.6,105.05 v1(164.8,105.05) ; J43.15@163.6,106.55 v1(164.8,106.55) ; J43.9@163.6,108.05 v1(164.788,108.05) ; J43.3@163.6,109.55 v1(164.788,109.55) ; v1(167.889,105.624) 167.902,105.637 168.728,105.637 D29.2@168.741,105.65 ; R203.2@169.425,101.321 v1(170.15,101.321) ; v1@180.273,179.677 v1(180.275,179.675) ; R345.1@183.6,183.035 v1(184.4,183.035) ; U45.3@185.05,176.3 185.053,176.297 185.717,176.297 v1(185.72,176.295) ; J44.3@197.527,157.95 v1(197.527,159.15) ; J44.10@199.432,154.35 v1(199.432,155.55) ; J44.16@201.337,154.35 v1(201.337,155.55) ; J44.22@203.242,154.35 v1(203.242,155.55) ; J27.2@203.75,186.427 v1(203.75,188.068) ; v1(204.5,181.65) U46.3@204.5,182.392 ; U46.8@204.5,183.209 v1(204.5,183.896) ; J44.28@205.147,154.35 v1(205.147,155.55) ; J27.5@205.25,186.427 v1(205.25,188.068) ; J27.8@206.75,186.427 v1(206.75,188.068) ; J44.34@207.052,154.35 v1(207.052,155.55) ; v1(207.5,181.65) U53.3@207.5,182.392 ; U53.8@207.5,183.209 v1(207.5,183.884) ; J27.11@208.25,186.427 v1(208.25,188.068) ; J44.40@208.957,154.35 v1(208.957,155.55) ; J27.16@210.75,186.427 v1(210.75,188.068) ; v1(211.5,181.65) U47.3@211.5,182.392 ; U47.8@211.5,183.209 v1(211.5,183.884) ; J44.50@212.132,154.35 v1(212.132,155.55) ; v1(214.037,156.75) J44.55@214.037,157.95 ; D35.2@215.308,14.22 v1(216.033,14.22) ; J44.60@215.307,154.35 v1(215.307,155.55) ; B8.1@218.861,12.037 v1(218.861,13.214) ; D33.2@222.552,14.214 v1(223.277,14.214) ; B7.1@226.111,12.037 v1(226.111,13.214) ; D15.1@229.813,14.225 v1(230.538,14.225) ; B6.1@233.361,12.037 v1(233.361,13.214) ; D8.1@237.194,14.162 v1(237.919,14.162) ; B5.1@240.611,12.037 v1(240.611,13.214)
  Top Layer w0.35: D36.1@126.831,190.09 D36.1@126.838,190.09 v1(127.511,190.09)
  Top Layer w0.4: U8.4@21.465,83.425 21.472,83.432 22.467,83.432 v1@22.475,83.425 ; C47.1@23.717,83.783 v1(23.717,84.5) ; v1(30.562,82.775) v1@30.577,82.76 ; v1(36.87,80.666) U3.1@36.87,81.325 ; v1(37.775,177.859) U86.2@38.85,177.859 ; v1(40.28,142.6) C390.1@41.1,142.6 ; v1(40.3,191.3) 40.55,191.55 J23.B1/A12@40.55,192.623 ; C39.2@40.4,180.4 v1(41.188,180.4) ; v1(41.27,143.871) C389.1@42.09,143.871 ; v1(42.666,177.224) C41.2@42.666,178.011 ; U87.10@46.165,141.936 v1(46.165,143.36) ; R85.1@46.341,179.494 46.343,179.492 46.343,178.838 v1(46.346,178.835) ; J23.A1/B12@46.95,192.623 46.95,191.85 v1(47.5,191.3) ; v1(49.823,179.837) 49.831,179.846 49.831,180.619 D11.2@49.84,180.628 ; v1(68.109,167.909) 68.117,167.917 68.117,168.582 C96.1@68.124,168.589 ; v1(68.932,159.344) C155.2@68.932,160.024 ; R172.1@72.18,169.254 v1(72.18,169.934) ; v1(73.645,159.844) C149.1@74.325,159.844 ; v1(73.645,170.146) C153.1@74.325,170.146 ; R224.1@74.37,148.31 v1(74.37,149.31) ; R288.2@75.425,70.25 v1(75.425,71.225) ; R225.1@76.12,148.31 v1(76.12,149.31) ; C151.1@77.195,160.792 v1(77.875,160.792) ; R171.1@77.985,164.925 v1(77.985,165.604) ; v1@79.369,169.625 R155.1@80.075,169.625 ; v1(79.45,155.507) C150.1@80.13,155.507 ; v1(79.45,165.817) C154.1@80.13,165.817 ; R153.1@80.95,169.625 80.952,169.623 81.658,169.623 v1(81.66,169.621) ; R226.1@81.37,148.36 v1(81.37,149.36) ; v1@82.063,170.35 C176.2@82.063,171.057 ; C164.1@82.371,173.412 v2(82.371,174.25) ; v1(83,155.72) C152.1@83,156.4 ; C177.2@87.551,181.948 v1(88.181,181.948) ; R176.1@87.751,180.95 v1(88.381,180.95) ; C160.1@87.975,171.647 v1(88.605,171.647) ; C173.2@87.975,172.497 v1(88.605,172.497) ; R130.2@88.506,160.354 v1(88.506,161.258) ; v1(89.346,148.359) C108.1@90.026,148.359 ; C122.1@90.026,159.282 v1(90.026,159.962) ; C110.1@92.886,149.866 v1(92.886,150.546) ; v1(102.375,150.769) C104.1@102.375,151.449 ; v1(103.646,156.157) R126.1@103.646,156.837 ; R132.1@103.872,167.996 v1(103.872,168.675) ; v1(105.495,156.157) R127.1@105.495,156.837 ; Y3.4@105.684,166.618 v1(105.684,167.664) ; C126.2@106.495,170.37 v1(107.174,170.37) ; Y3.2@107.542,168.918 v1(108.587,168.918) ; C323.1@107.71,177.075 107.729,177.094 108.26,177.094 108.389,177.223 108.858,177.223 v1(108.86,177.225) ; C128.2@108.342,165.138 v1(109.021,165.138) ; v1(109.602,163.545) R133.1@109.602,164.225 ; v1(113.495,157.419) D20.2@114.346,157.419 ; v1(113.495,172.231) C324.1@113.495,172.911 ; v1(114.299,163.409) 114.322,163.432 114.322,165.019 D21.2@114.346,165.043 ; R142.1@117.898,163.04 v1(118.749,163.04) ; R143.1@117.975,170.403 v1(117.975,171.469) ; v1(118.517,179.457) Q28.2@118.517,180.392 ; v1(119.069,157.351) C145.1@119.069,158.03 ; v1(119.112,164.86) C146.1@119.112,165.559 ; v1(121.149,160.89) U28.2@122.154,160.89 ; v1(121.149,168.413) U29.2@122.154,168.413 ; v1(122.321,178.765) R405.2@122.321,179.7 ; D45.2@126.482,197.8 v1(126.482,198.651) ; C328.1@127.085,187.9 v1(127.764,187.9) ; C35.1@127.546,186.65 v1(128.444,186.65) ; v1(133.063,37.435) 133.063,38.095 C234.1@133.065,38.097 ; v1(133.302,41.347) 133.323,41.368 C235.1@133.323,42.213 ; v1(134.352,36.975) U57.1@134.352,38.065 ; v1(136.18,175.486) Q29.2@136.18,176.486 ; R404.1@137.03,178.838 137.032,178.84 137.032,179.505 v1(137.035,179.508) ; v1(139.6,187.5) U84.8@139.6,188.258 ; U84.3@139.6,189.075 v1(139.6,189.905) ; C65.1@139.885,162.933 v1(139.885,163.602) ; v1(140.741,15.275) R185.2@141.858,15.275 ; v1(141.27,173.136) R101.2@141.27,174.086 ; v1(142.121,48.16) R378.1@142.121,48.885 ; v1(142.701,179.528) 142.704,179.524 143.542,179.524 D18.2@143.545,179.521 ; v1(144.321,48.36) C286.2@144.321,49.085 ; v1(145.156,48.36) C196.2@145.156,49.085 ; R114.1@147.142,181.808 147.807,181.808 v1(147.81,181.805) ; v1(147.513,163.675) v1(147.513,163.675) 147.514,163.001 C66.1@147.515,163 ; U10.1@148.98,162.775 148.99,162.775 v1(148.99,163.335) ; C95.1@150.074,173.962 150.739,173.962 v1(150.741,173.96) ; C94.1@150.074,176.617 150.074,177.282 v1(150.076,177.285) ; v1(152.323,43.633) R252.1@153.324,43.633 ; v1(152.323,46.933) R251.1@153.324,46.933 ; C69.1@155.125,162.933 v1(155.125,163.602) ; C97.1@157.049,176.121 157.714,176.121 v1(157.716,176.118) ; D25.2@158.7,3.755 v1(158.7,4.518) ; v1(161.397,42.618) U58.5@162.637,42.618 ; U58.4@162.637,41.983 v1(163.877,41.983) ; v1(164.145,177.43) 164.147,177.433 C304.2@164.147,178.098 ; C236.1@165.04,43.251 v1(165.787,43.251) ; v1(166.223,151.85) C354.1@167.023,151.85 ; v1(166.223,152.675) C353.1@167.023,152.675 ; C306.2@166.902,180.548 167.567,180.548 v1(167.57,180.545) ; C310.2@166.902,181.448 167.567,181.448 v1(167.57,181.445) ; C309.2@166.902,183.832 167.567,183.832 v1(167.57,183.83) ; v1(168.325,155.755) U60.10@169.5,155.755 ; R272.2@168.875,30 v1(168.875,30.675) ; v1(171.175,21) Q17.2@171.175,21.95 ; v1(171.662,27.775) C237.1@172.437,27.775 ; U25.3@172.15,33.025 v1(172.15,34.114) ; v1(174.175,151.855) U60.1@175.4,151.855 ; v1(174.175,155.755) U60.7@175.4,155.755 ; v1(175.63,177.595) 175.633,177.592 C302.1@176.298,177.592 ; v1(175.63,178.884) 175.633,178.882 C308.2@176.298,178.882 ; v1(175.725,18.611) U40.3@175.725,19.7 ; R344.1@184.577,172.098 185.242,172.098 v1(185.245,172.095) ; v1(194.125,184.917) R267.2@194.125,185.817 ; v1(196.65,184.992) C346.1@196.65,186.217 ; v1(197.294,163.2) C208.1@198.172,163.2 ; v1@200.625,181.653 R256.2@200.625,182.317 ; v1@201.6,181.653 R115.2@201.6,182.317 ; C206.1@203.875,160.778 v1@203.875,161.442 ; v1(208.125,93.226) C229.1@208.385,93.226 ; v1(212.05,177.567) R270.2@212.05,178.267 ; v1(212.835,179.567) C345.1@212.835,180.267 ; v1(213.55,177.142) C350.1@213.55,177.842 ; C359.1@213.725,136.66 v1@213.725,137.404 ; R440.1@214.375,180.817 v1(214.375,181.517) ; v1(214.6,177.142) C349.1@214.6,177.842 ; R441.1@215.375,180.817 v1(215.375,181.517) ; v1(215.675,177.142) C348.1@215.675,177.842 ; v1(219.525,175.667) C347.1@219.525,176.367 ; v1(222.196,105.32) 222.199,105.318 C311.1@222.864,105.318 ; v1(222.481,83.395) 222.483,83.393 C317.1@223.148,83.393 ; R473.2@222.484,138.731 v1@223.228,138.731 ; R474.2@222.486,137.778 223.231,137.778 v1(223.234,137.775) ; v1(223.664,106.19) 223.718,106.19 223.943,105.965 U81.1@225.12,105.965 U81.1@225.122,105.965 ; v1(223.759,74.653) 223.762,74.651 R370.1@224.427,74.651 ; v1(223.759,75.673) 223.762,75.67 R369.1@224.427,75.67 ; v1(223.759,76.603) 223.762,76.601 R368.1@224.427,76.601 ; v1(223.76,94.305) 223.762,94.302 R362.1@224.427,94.302 ; v1(223.76,95.324) 223.762,95.322 R361.1@224.427,95.322 ; v1(223.76,96.255) 223.762,96.253 R360.1@224.427,96.253 ; v1(223.948,84.265) 224.002,84.265 224.227,84.04 U88.1@225.404,84.04 U88.1@225.407,84.04 ; C319.1@235.732,77.005 236.397,77.005 v1(236.399,77.003) ; C313.1@235.732,96.657 236.397,96.657 v1(236.4,96.654) ; C318.1@235.832,77.896 236.497,77.896 v1(236.499,77.893) ; C312.1@235.832,97.548 236.497,97.548 v1(236.5,97.545) ; R366.1@236.601,94.917 236.609,94.909 237.258,94.909 v1(237.268,94.899) ; R374.1@236.771,75.296 237.436,75.296 v1(237.439,75.293) ; v1(241.94,91.072) 242.283,90.73 J71.1@243.4,90.73 ; v1(241.94,110.332) 242.283,109.99 J70.1@243.4,109.99 ; v1@242.145,87.75 J71.7@243.37,87.75 ; v1(242.145,107.03) 242.165,107.01 243.37,107.01 J70.7@243.397,106.983 ; v1(245.19,82.233) J71.18@246.397,82.233 ; v1(245.19,86.233) J71.10@246.397,86.233 ; v1(245.19,89.233) J71.4@246.397,89.233 ; v1(245.19,101.493) J70.18@246.397,101.493 ; v1(245.19,105.493) J70.10@246.397,105.493 ; v1(245.19,108.493) J70.4@246.397,108.493
  Top Layer w0.5: v1(1.9,84.253) C14.1@2.972,84.253 ; v1(4.128,77.635) R31.1@4.128,78.375 ; R447.2@5.004,11.854 v1(5.004,12.8) ; C283.1@6.862,145.455 v1(6.862,146.705) ; v1(8.011,15.838) C215.2@8.957,15.838 ; C187.1@9.362,145.455 v1(9.362,146.705) ; v1(10.525,73.35) R42.2@11.475,73.35 ; v1(12.9,72) 12.915,71.985 13.59,71.985 C17.1@13.6,71.975 ; U50.3@13.511,8.663 v1(13.511,9.663) ; v1(15.711,81.775) C49.1@16.45,81.775 ; v1(15.711,83.775) R59.1@16.45,83.775 ; v1(16.725,85.7) Q8.2@17.65,85.7 ; R357.2@17.661,8.138 v1(17.661,8.888) ; C20.1@18.7,112.175 v1(18.7,113.225) ; v1(18.866,99.686) C22.1@18.866,100.425 ; v1(19.725,80.05) C48.1@20.45,80.05 ; v1@19.869,99.721 C27.1@19.869,100.428 ; C12.1@20.725,94.35 v1(21.464,94.35) ; U49.8@20.921,17.103 v1(22.303,17.103) ; C210.1@21.924,22.305 v1(22.674,22.305) ; C23.1@21.95,112.2 v1(21.95,113.25) ; v1(22.075,96.325) R303.1@23.025,96.325 ; C183.1@22.54,136.94 22.557,136.923 23.773,136.923 ; C185.1@22.54,139.44 23.03,138.95 v3(23.92,138.95) ; R47.1@22.95,105.475 v1(23.709,105.475) ; C301.1@23.5,151.825 23.506,151.819 24.206,151.819 v1(24.225,151.8) ; v1(24.8,191.597) J65.B1/A12@24.8,192.622 ; R312.2@24.942,124.925 v1(25.681,124.925) ; v1(24.999,18.373) U49.2@26.382,18.373 ; R34.1@25.045,101.232 v1(26.02,101.232) ; v1(25.15,93.675) R16.1@26.05,93.675 ; v1(25.4,153.375) v1(28.45,153.375) ; R304.1@25.842,121.925 v1(26.792,121.925) ; C269.2@25.863,123.502 v1(26.813,123.502) ; v1(27.45,15.825) C216.2@28.396,15.825 ; v1(27.55,87.575) R15.1@27.55,88.475 ; C212.1@28.225,20.65 v1(28.225,21.425) ; C214.1@29.2,20.65 v1(29.2,21.425) ; v1(31.2,191.6) J65.A1/B12@31.2,192.622 ; v1(31.375,153.34) 31.392,153.357 33.108,153.357 U104.2@33.125,153.375 ; U48.8@31.919,19.595 v1(33.302,19.595) ; v1(32.125,73.825) R56.2@32.125,74.55 ; C50.2@32.725,79.45 v1(33.725,79.45) ; U51.3@32.95,8.65 v1(32.95,9.65) ; U68.4@33.169,31.19 v1(34.552,31.19) ; U67.4@33.173,49.605 v1(34.556,49.605) ; v1(34.255,117.355) 34.274,117.374 34.274,119.149 C1.1@34.55,119.425 ; U1.2@34.6,122.675 U1.4@34.6,128.875 ; v1(35.998,20.865) U48.2@37.38,20.865 ; C252.1@36.046,27.36 v1(36.795,27.36) ; C251.1@36.05,45.775 v1(36.8,45.775) ; U66.2@36.248,34.5 36.298,34.55 37.433,34.55 37.599,34.715 C250.1@37.845,34.715 ; U66.6@36.248,39.58 v1(37.631,39.58) ; U66.7@36.248,40.85 v1(37.631,40.85) ; U66.8@36.248,42.12 v1(37.631,42.12) ; v1(36.25,71.175) Q4.2@36.25,72.075 ; U65.2@36.253,52.915 36.303,52.965 37.438,52.965 37.604,53.13 C249.1@37.85,53.13 ; U65.6@36.253,57.995 v1(37.635,57.995) ; U65.7@36.253,59.265 v1(37.635,59.265) ; U65.8@36.253,60.535 v1(37.635,60.535) ; v1(36.794,117.175) 36.794,118.219 C4.1@36.925,118.35 ; R356.2@37.1,8.125 v1(37.1,8.875) ; C285.1@37.65,155.675 v1(38.825,155.675) ; C250.1@37.845,34.765 38.787,34.765 38.787,34.047 v1(38.775,34.035) ; C249.1@37.85,53.18 38.791,53.18 38.791,52.461 v1(38.78,52.45) ; C8.1@38.3,80.975 v1(39.009,80.975) ; C284.1@38.55,151.05 v1(39.65,151.05) ; R292.1@39.096,37.01 v1(39.845,37.01) ; R291.1@39.1,55.425 v1(39.85,55.425) ; C211.1@40.975,21 v1(41.75,21) ; C213.1@40.975,22.125 v1(41.75,22.125) ; v1(42.015,171.525) Y1.4@42.99,171.525 ; Y1.2@45.29,169.675 v1(46.365,169.675) ; v1(47.291,184.788) U13.2@47.291,185.788 ; C73.2@48.837,179.109 v1(49.492,179.109) ; U35.8@72.585,167.504 72.649,167.44 72.649,166.353 72.941,166.06 72.989,166.06 73.29,165.759 v2(73.29,165.604) ; U36.8@78.39,163.167 78.454,163.103 78.454,162.016 78.746,161.723 78.794,161.723 79.095,161.422 v2(79.095,161.267) ; U26.8@88.286,156.581 88.349,156.517 88.349,155.43 88.642,155.137 88.69,155.137 88.991,154.836 v2(88.991,154.681) ; v1(142.319,23.425) C193.1@143.015,23.425 ; v1(142.322,21.7) C368.1@143.018,21.7 ; v1(142.322,22.575) C366.1@143.018,22.575 ; v1(142.322,24.275) C195.1@143.018,24.275 ; v1(142.458,4.2) C369.1@143.155,4.2 ; v1(142.459,5.015) C367.1@143.155,5.015 ; v1(142.459,6.625) C194.1@143.155,6.625 ; v1(142.459,7.425) C192.1@143.155,7.425 ; v1(142.462,5.805) C365.1@143.158,5.805 ; v1(152.796,94.049) C377.1@153.493,94.049 ; v1(152.796,94.896) C375.1@153.493,94.896 ; v1(152.796,108.3) C203.1@153.493,108.3 ; v1(152.796,109.084) C202.1@153.493,109.084 ; v1(152.796,109.9) C201.1@153.493,109.9 ; v1(152.796,110.693) C200.1@153.493,110.693 ; v1(152.796,111.529) C380.1@153.493,111.529 ; v1(152.796,112.329) C378.1@153.493,112.329 ; v1(152.8,91.55) C382.1@153.497,91.55 ; v1(152.8,92.4) C381.1@153.497,92.4 ; v1(152.8,93.2) C379.1@153.497,93.2 ; v1(152.804,103.15) C376.1@153.5,103.15 ; v1(152.804,104.05) C374.1@153.5,104.05 ; v1(152.804,104.85) C388.1@153.5,104.85 ; v1(152.804,105.75) C387.1@153.5,105.75 ; v1(152.804,106.55) C386.1@153.5,106.55 ; v1(152.804,107.45) C385.1@153.5,107.45 ; v1(218.53,179.817) U80.2@219.505,179.817 ; R218.2@222.6,180.792 v1(223.575,180.792) ; v1(236.765,177.335) C220.1@237.465,177.335 ; v1(239.201,99.441) C316.1@239.994,99.441 ; C222.1@239.275,178.975 v1(239.275,179.754) ; v1(239.291,84.196) C321.1@240.029,84.196 ; v1(239.313,103.435) C315.1@240.05,103.435 ; v1(239.325,80.175) C322.1@240.063,80.175 ; C217.1@240.075,178.975 v1(240.075,179.754)
  Top Layer w0.6: v1(15.373,155.372) L1.4@16.779,155.372 ; v1(16.779,157.214) L1.4@16.779,155.372 ; v1(16.79,153.541) L1.4@16.79,155.372 ; v1(17.75,155.372) L1.4@16.79,155.372 ; L1.4@16.779,155.372 L1.4@16.79,155.372
  Bottom Layer w0.2: U96.5@107.71,175.775 108.61,175.775 v1(108.86,176.025) ; U96.21@108.91,174.825 109.11,174.625 U96.20@109.11,173.875 ; U96.21@108.91,177.225 109.11,177.425 U96.11@109.11,178.175
  Bottom Layer w0.25: v1(25.375,195.185) R319.2@26.775,195.185 R319.2@26.764,195.175 ; C288.1@29.1,195.475 v1(30.5,195.475) ; v1(49.95,183.65) R148.2@49.95,184.52 ; C148.1@52.45,184.57 52.74,184.28 v1(52.74,183.536) ; v1(72.821,182.753) Q15.4@72.821,183.298 ; Q15.1@73.821,181.948 v1(74.366,181.948) ; XB1.1@74.9,8.8 v1(74.9,13.46) ; R352.2@91.649,167.443 v1(91.649,168.186) ; C111.1@97.796,160.44 97.796,161.249 ; v5(98.818,161.57) 98.818,161.49 98.576,161.249 C112.1@98.576,160.44 99.385,160.44 ; v1(101.525,191.7) U31.8@101.525,192.466 U31.3@101.525,193.283 v1(101.525,194.125) ; C106.1@105.424,161.8 105.559,161.665 105.795,161.665 106.059,161.4 106.059,161.005 106.112,160.952 v1(106.113,160.951) ; 228.275,171.383 228.275,172.128 ; 228.275,180.64 228.275,181.386 ; 228.275,182.481 228.275,183.226 ; 228.294,169.575 228.294,170.32
  Bottom Layer w0.3: C124.2@105.424,160.953 v1@106.112,160.952 ; v1(207.5,183.884) 207.5,184.357 207.9,184.757 R399.1@208.6,184.757
  Bottom Layer w0.4: R82.2@34.3,197.66 v1(34.3,198.585) ; C71.1@36.65,197.26 v1(36.65,198.485) ; v1(80.2,181.433) U38.8@80.2,182.108 ; U38.3@80.2,182.925 80.212,182.937 80.212,183.654 v1(80.225,183.667) ; v1(81.4,190.415) R179.2@81.4,191.365 ; v1(83.725,190.626) C186.1@83.725,191.865 ; v1(85.4,181.466) U39.8@85.4,182.141 ; U39.3@85.4,182.958 85.421,182.979 85.421,183.679 v1(85.443,183.7) ; v1(87.497,179.44) Y2.4@88.472,179.44 ; C159.2@89.272,175.63 89.287,175.615 89.885,175.615 v1(89.9,175.6) ; C162.2@89.5,180.9 v1(89.5,181.6) ; Y2.2@90.322,177.14 90.362,177.1 v1(91.3,177.1) ; v1(92.868,165.005) 92.87,165.005 93.016,164.86 C113.1@93.822,164.86 ; v1(93.122,165.694) C118.1@93.822,165.694 ; v1(93.122,166.56) C105.1@93.822,166.56 ; J30.12@94.825,5.975 v1(96.068,5.975) ; v1(95.812,20.575) J30.12@97.055,20.575 ; U18.2@105.05,28.83 v1(105.05,29.88) ; v1(106.6,21.25) J30.3@106.6,22.525 ; C91.1@107.3,25.52 v1(107.96,25.52) ; v1(107.454,29.88) C90.1@108.114,29.88 ; C280.1@108.066,28.17 v1(108.066,28.83) ; C282.1@108.924,28.17 v1(108.924,28.83) ; v1(111.2,28.83) U16.2@111.2,29.88 ; R460.2@111.95,33.8 v1(112.61,33.8) ; v1(112.172,190.987) D37.1@112.834,190.987 ; R98.1@112.194,25.035 v1(112.854,25.035) ; R97.1@112.194,26.035 v1(112.854,26.035) ; v1(112.834,187.126) D38.1@112.834,187.787 v1(113.495,187.787) ; v1(112.834,191.648) D37.1@112.834,190.987 ; v1(113.495,190.987) D37.1@112.834,190.987 ; J30.6@114.1,22.525 v1(114.1,23.825) ; U17.2@116.525,28.83 v1(116.525,29.88) ; v1(120.882,5.975) J30.12@122.125,5.975 ; J30.12@122.125,20.575 v1(123.368,20.575) ; J42.9@125.69,12.275 v1(125.69,13.245) ; J42.9@125.875,5.885 v1(125.875,6.855) ; J42.9@127.12,19.235 v1(127.12,20.205) ; J42.C5@128.19,12.535 v1(128.19,13.505) ; J42.9@136.19,18.555 v1(136.876,19.241) ; J42.9@138.125,5.885 v1(138.125,6.855) ; J42.9@138.31,12.278 v1(138.31,13.248) ; v1(138.669,19.905) C364.1@139.908,19.905 ; C197.2@140.741,14.592 v1(140.741,15.275) ; v1(140.891,8.193) U42.2@140.891,9.163 ; C362.1@144.014,24.925 v1(144.014,26.164) ; C363.1@144.314,10.022 v1(144.314,11.26) ; C361.1@146.63,10.022 146.632,10.019 v1(147.91,10.019) ; v1(157.939,56.916) Q6.2@157.939,57.748 ; v1(162.232,55.999) C358.1@162.232,56.659 ; R190.1@164.485,55.471 v1(165.146,55.471) ; U63.3@164.75,60.148 v1(165.41,60.148)
  Bottom Layer w0.5: C330.1@107.81,195.135 v1(109.049,195.135) C329.1@111.09,195.135 ; R398.2@108.21,197.91 v1(109.16,197.91) R397.2@110.69,197.91 ; C101.1@143.5,197.9 v1(144.789,197.9) ; R120.2@143.9,195.55 v1(144.789,195.55) ; v1(152.804,104.05) 154.85,104.05 156.3,105.5 C384.1@156.4,105.5 ; v1(158.749,104.31) C383.1@158.749,105.5 ; v1(161.076,104.31) C372.1@161.076,105.5 ; C370.1@163.4,105.5 163.85,105.05 v1(164.8,105.05) ; v1(213.75,97.025) 213.75,97.052 213.938,97.24 213.938,97.73 C232.1@213.948,97.74 ; C231.1@215.075,93.53 215.085,93.52 215.085,93.042 215.25,92.877 v1(215.25,92.85) ; v1@218.37,94.355 218.397,94.355 218.587,94.545 218.985,94.545 C360.1@218.995,94.555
